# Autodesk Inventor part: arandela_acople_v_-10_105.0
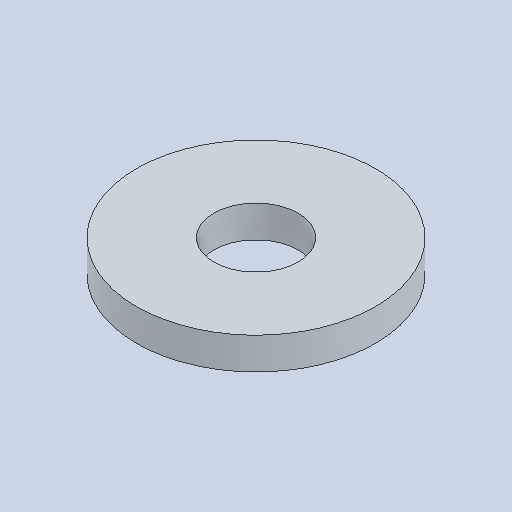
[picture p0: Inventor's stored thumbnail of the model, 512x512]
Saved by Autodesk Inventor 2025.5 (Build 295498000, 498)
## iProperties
Created: 2026-10
Part Number: arandela_acople_v_-10_105.0
Material: Genérico
Document SubType Name: Modeling
Designer: Luis M
Density: 1 g/cm^3
Appearance: Valor por defecto
Author: Luis M
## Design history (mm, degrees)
feature "Base1"
node "Sólido1"
